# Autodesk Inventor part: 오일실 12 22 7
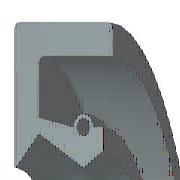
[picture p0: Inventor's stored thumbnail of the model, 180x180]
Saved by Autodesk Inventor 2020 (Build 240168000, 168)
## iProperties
Created: 2012-02
Part Number: 오일실 12 22 7
Material: 고무
Description: 오일-실
Document SubType Name: Modeling
Standard: KS B 2804
Designer: mduedu
Standards Organization: KS
Language: ko-KR
Size Designation: D - 12 22 7
Categories: <MemberInstance><Categories><Category DisplayName="샤프트 부품" InternalName="7f7aeb1f-a693-4053-b835-cee3144e0d98" Mnemonic="SHFT"><Category DisplayName="실링" Intern
Density: 0.93 g/cm^3
Mass: 1.25383 g
Surface Area: 18.4996 cm^2
Volume: 1.3482 cm^3
Appearance: 고무 - 검은색 - 버전 1.1
IsCustomPart: 1
Author: mduedu
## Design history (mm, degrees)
revolve "본체" stored, may be unused: angle "d17" = 90 deg
revolve "스프링1" stored, may be unused: angle "d18" = 90 deg
body "Solid1"
sketch "스케치1"
  geometry: L1 (0, 11)-(7, 11); L2 (7, 9.25)-(1.75, 9.25); L3 (1.75, 7.75)-(4.9, 6); L4 (4.9, 6)-(0, 6); L5 (0, 0)-(9.586, 0) reference; L6 (4.9, 6)-(6.3, 6.875); L7 (0, 18)-(0, -3) reference; L8 (-1.941, 0)-(11.507, 0) reference; L9 (4.2, 8.1)-(1.75, 8.59); L10 (1.75, 8.59)-(1.75, 9.25); L11 (0, 11)-(0, 6.088); L12 (4.9, 6)-(0, 6); L13 (1.75, 7.75)-(0.152, 6.028); L14 (7, 11)-(7, 9.25); L15 (5.6, 8.1)-(6.3, 8.1); L16 (6.3, 8.1)-(6.3, 6.875); C1 r 0.455 at (4.9, 8.1); A1 r 0.7 centre (4.9, 8.1) between (5.6, 8.1) and (4.2, 8.1); A2 r 0.088 centre (0.088, 6.088) between (0, 6.088) and (0.152, 6.028); 1 further point
  constraints: 28 end point, 5 horizontal alignment, 5 point on line, 4 point on circle, 4 vertical alignment, 3 centre point, 3 tangent, 2 collinear, 2 horizontal, 2 perpendicular, 1 coincident, 1 parallel
  dimensions: "d0" = 22 diameter of L1 L5 (= SD2); "d1" = 1.75 distance of L1.end L2.start (= SD); "d2" = 0.91 diameter of C1 (= SPDI); "d3" = 1.4 diameter of A1 (= SPDA); "d4" = 12 diameter of L3.end L5 (= NND); "d5" = 15.5 diameter of L3.start L5 (= TKDM); "d7" = 17.18 diameter of L9.end L5 (= TKDM + 0.24 x SWDT); "d8" = 1.75 distance between parallel lines of L11 L10 (= SD); "d9" = 4.9 distance from line of L11 C1.centre (= SPDST); "d10" = 16.2 diameter of C1.centre L5 (= HLDM); "d11" = 0.0875 radius of A2 (= 0.25 x LAB); "d12" = 6.3 distance between parallel lines of L11 L16 (= SDI); "d13" = 13.75 diameter of L6.end L5 (= ABDM); "d14" = 7 distance from line of L11 L1.end (= SWDT)
fillet "모깎기1" dims "d6" = 0.3 (= RR)
other parameters: "SD2" = 22 [user parameter; used in 1 equation term], "SWDT" = 7 [user parameter; used in 2 equation terms], "RR" = 0.3 [user parameter; used in 1 equation term], "SD" = 1.75 [user parameter; used in 2 equation terms], "NND" = 12 [user parameter; used in 1 equation term], "SPDA" = 1.4 [user parameter; used in 1 equation term], "SPDI" = 0.91 [user parameter; used in 1 equation term], "TKDM" = 15.5 [user parameter; used in 2 equation terms], "HLDM" = 16.2 [user parameter; used in 1 equation term], "ABDM" = 13.75 [user parameter; used in 1 equation term], "SDI" = 6.3 [user parameter; used in 1 equation term], "SPDST" = 4.9 [user parameter; used in 1 equation term], "LAB" = 0.35 [user parameter; used in 1 equation term], "d15" = 0, "d16" = 0, "d19" = 0
